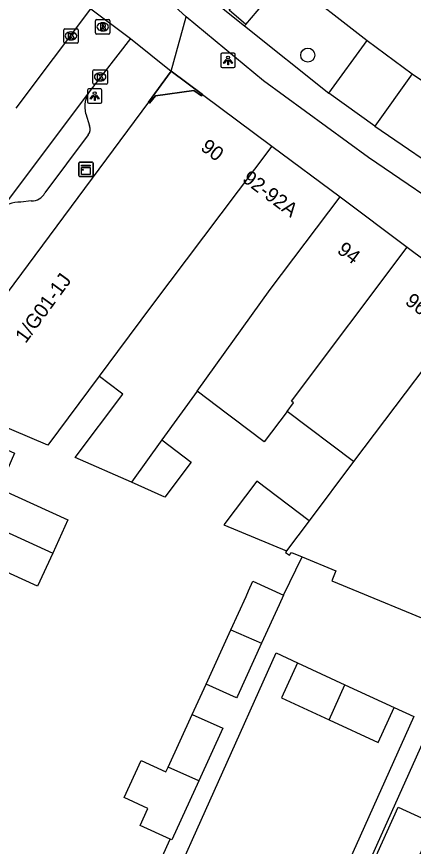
# Model space of a CAD drawing. Extents: x 161845 to 162341, y 381620 to 382158.
# Drawn here: x 162123.1 to 162150.7, y 381792.3 to 381850 of the extents above; entities that cross this region are included whole.
import ezdxf

# ---------------------------------------------------------------- set-up
doc = ezdxf.new("R2010")
doc.units = 0
for name, color, linetype in [('IMGEO_Berm_groen', 7, 'Continuous'), ('IMGEO_Boom', 7, 'Continuous'), ('IMGEO_Groenvoorziening', 7, 'Continuous'), ('IMGEO_Kast', 7, 'Continuous'), ('IMGEO_Kolk', 7, 'Continuous'), ('IMGEO_Lichtpunt', 7, 'Continuous'), ('IMGEO_Pand', 7, 'Continuous'), ('IMGEO_Pand_nummerreeks', 7, 'Continuous'), ('IMGEO_Pand_overbouw', 7, 'Continuous'), ('IMGEO_Rijbaan_lokaal_gesloten', 7, 'Continuous'), ('IMGEO_Rijbaan_lokaal_open', 7, 'Continuous'), ('IMGEO_Rioolput', 7, 'Continuous'), ('IMGEO_Voetpad_gesloten', 7, 'Continuous'), ('IMGEO_Voetpad_open', 7, 'Continuous')]:
    doc.layers.add(name, color=color, linetype=linetype)

msp = doc.modelspace()

# ---------------------------------------------------------------- linework, layer by layer
at = {"layer": 'IMGEO_Berm_groen'}
for points in [[(162139.024, 381849.428), (162140.224, 381850.815)], [(162138.949, 381849.346), (162139.024, 381849.428)]]:
    msp.add_lwpolyline(points, dxfattribs=at)
at = {"layer": 'IMGEO_Boom'}
msp.add_circle((162143.338, 381847.307), 0.489, dxfattribs=at)
at = {"layer": 'IMGEO_Groenvoorziening'}
msp.add_lwpolyline([(162139.024, 381849.428), (162137.867, 381850.429), (162139.067, 381851.816), (162139.757, 381851.219), (162140.224, 381850.815)], dxfattribs=at)
at = {"layer": 'IMGEO_Kast'}
for p, q in [((162127.417, 381838.946), (162127.417, 381839.787)), ((162127.417, 381839.787), (162127.417, 381838.946)), ((162127.492, 381839.871), (162128.333, 381839.871)), ((162128.333, 381839.871), (162127.492, 381839.871)), ((162128.417, 381839.796), (162128.417, 381838.955)), ((162128.417, 381838.955), (162128.417, 381839.796)), ((162128.342, 381838.871), (162127.501, 381838.871)), ((162127.501, 381838.871), (162128.342, 381838.871))]:
    msp.add_line(p, q, dxfattribs=at)
for points in [[(162127.612, 381839.661), (162128.212, 381839.661), (162128.212, 381839.576), (162127.612, 381839.576), (162127.612, 381839.661)], [(162127.612, 381839.486), (162128.212, 381839.486), (162128.212, 381838.997), (162127.612, 381838.997), (162127.612, 381839.486)]]:
    msp.add_lwpolyline(points, dxfattribs=at)
msp.add_circle((162127.696, 381839.335), 0.0377, dxfattribs=at)
for centre, start, end in [((162127.495, 381839.793), 92.4484, 184.28452), ((162127.495, 381839.793), 92.4484, 184.28452), ((162128.339, 381839.793), 2.4484, 94.28452), ((162128.339, 381839.793), 2.4484, 94.28452), ((162127.495, 381838.949), 182.4484, 274.28452), ((162127.495, 381838.949), 182.4484, 274.28452), ((162128.339, 381838.949), 272.4484, 4.28452), ((162128.339, 381838.949), 272.4484, 4.28452)]:
    msp.add_arc(centre, 0.0779, start, end, dxfattribs=at)
at = {"layer": 'IMGEO_Kolk'}
for p, q in [((162126.37, 381848.212), (162126.37, 381849.064)), ((162126.445, 381849.138), (162127.297, 381849.138)), ((162126.858, 381848.918), (162126.883, 381848.918)), ((162127.371, 381849.064), (162127.371, 381848.212)), ((162127.297, 381848.138), (162126.445, 381848.138)), ((162126.881, 381848.358), (162126.856, 381848.358)), ((162128.401, 381845.365), (162128.401, 381846.217)), ((162128.476, 381846.291), (162129.328, 381846.291)), ((162128.889, 381846.071), (162128.914, 381846.071)), ((162129.402, 381846.217), (162129.402, 381845.365)), ((162129.328, 381845.291), (162128.476, 381845.291)), ((162128.912, 381845.511), (162128.887, 381845.511))]:
    msp.add_line(p, q, dxfattribs=at)
for points in [[(162126.37, 381848.212), (162126.37, 381849.064)], [(162126.445, 381849.138), (162127.297, 381849.138)], [(162126.691, 381848.838), (162126.814, 381848.838), (162126.814, 381848.687), (162126.944, 381848.838), (162127.108, 381848.838), (162126.962, 381848.687), (162127.115, 381848.438), (162126.963, 381848.438), (162126.878, 381848.602), (162126.814, 381848.535), (162126.814, 381848.438), (162126.691, 381848.438), (162126.691, 381848.838)], [(162127.371, 381849.064), (162127.371, 381848.212)], [(162127.297, 381848.138), (162126.445, 381848.138)], [(162128.401, 381845.365), (162128.401, 381846.217)], [(162128.476, 381846.291), (162129.328, 381846.291)], [(162128.722, 381845.991), (162128.845, 381845.991), (162128.845, 381845.84), (162128.975, 381845.991), (162129.139, 381845.991), (162128.993, 381845.84), (162129.146, 381845.591), (162128.994, 381845.591), (162128.909, 381845.755), (162128.845, 381845.688), (162128.845, 381845.591), (162128.722, 381845.591), (162128.722, 381845.991)], [(162129.402, 381846.217), (162129.402, 381845.365)], [(162129.328, 381845.291), (162128.476, 381845.291)]]:
    msp.add_lwpolyline(points, dxfattribs=at)
for centre, start, end in [((162126.447, 381849.062), 91.55205, 178.44795), ((162126.447, 381849.062), 91.55205, 178.44795), ((162127.295, 381849.062), 1.55205, 88.44795), ((162127.295, 381849.062), 1.55205, 88.44795), ((162126.447, 381848.214), 181.55205, 268.44795), ((162126.447, 381848.214), 181.55205, 268.44795), ((162127.295, 381848.214), 271.55205, 358.44795), ((162127.295, 381848.214), 271.55205, 358.44795), ((162128.478, 381846.215), 91.55205, 178.44795), ((162128.478, 381846.215), 91.55205, 178.44795), ((162129.326, 381846.215), 1.55205, 88.44795), ((162129.326, 381846.215), 1.55205, 88.44795), ((162128.478, 381845.367), 181.55205, 268.44795), ((162128.478, 381845.367), 181.55205, 268.44795), ((162129.326, 381845.367), 271.55205, 358.44795), ((162129.326, 381845.367), 271.55205, 358.44795)]:
    msp.add_arc(centre, 0.0765, start, end, dxfattribs=at)
for centre, major_axis, ratio, start_param, end_param in [((162126.857, 381848.638), (-0.387, 0.002), 0.722429, 4.712389, 7.853982), ((162126.882, 381848.638), (-0.39, 0.002), 0.717154, 1.570796, 4.712389), ((162128.888, 381845.791), (-0.387, 0.002), 0.722429, 4.712389, 7.853982), ((162128.913, 381845.791), (-0.39, 0.002), 0.717154, 1.570796, 4.712389)]:
    msp.add_ellipse(centre, major_axis=major_axis, ratio=ratio, start_param=start_param, end_param=end_param, dxfattribs=at)
at = {"layer": 'IMGEO_Lichtpunt'}
for p, q in [((162137.299, 381847.342), (162137.299, 381846.535)), ((162137.299, 381847.342), (162137.299, 381846.535)), ((162138.201, 381847.437), (162137.393, 381847.437)), ((162138.201, 381847.437), (162137.393, 381847.437)), ((162138.295, 381846.535), (162138.295, 381847.342)), ((162138.295, 381846.535), (162138.295, 381847.342)), ((162137.393, 381846.441), (162138.201, 381846.441)), ((162137.393, 381846.441), (162138.201, 381846.441)), ((162128.022, 381844.86), (162128.022, 381844.053)), ((162128.022, 381844.86), (162128.022, 381844.053)), ((162128.924, 381844.955), (162128.116, 381844.955)), ((162128.924, 381844.955), (162128.116, 381844.955)), ((162129.018, 381844.053), (162129.018, 381844.86)), ((162129.018, 381844.053), (162129.018, 381844.86)), ((162128.116, 381843.959), (162128.924, 381843.959)), ((162128.116, 381843.959), (162128.924, 381843.959))]:
    msp.add_line(p, q, dxfattribs=at)
for points in [[(162137.673, 381847.006), (162137.712, 381846.978), (162137.524, 381846.716), (162137.486, 381846.743), (162137.673, 381847.006)], [(162137.775, 381846.958), (162137.822, 381846.958), (162137.822, 381846.636), (162137.775, 381846.636), (162137.775, 381846.958)], [(162137.885, 381846.978), (162137.923, 381847.005), (162138.11, 381846.743), (162138.071, 381846.715), (162137.885, 381846.978)], [(162128.396, 381844.524), (162128.435, 381844.496), (162128.247, 381844.234), (162128.209, 381844.261), (162128.396, 381844.524)], [(162128.498, 381844.476), (162128.545, 381844.476), (162128.545, 381844.154), (162128.498, 381844.154), (162128.498, 381844.476)], [(162128.608, 381844.496), (162128.646, 381844.523), (162128.833, 381844.261), (162128.794, 381844.233), (162128.608, 381844.496)]]:
    msp.add_lwpolyline(points, dxfattribs=at)
for centre in [(162137.798, 381847.14), (162128.521, 381844.658)]:
    msp.add_circle(centre, 0.0994, dxfattribs=at)
for centre, start, end in [((162137.393, 381847.342), 90, 180), ((162137.393, 381847.342), 90, 180), ((162138.201, 381847.342), 0, 90), ((162138.201, 381847.342), 0, 90), ((162137.393, 381846.535), 180, 270), ((162137.393, 381846.535), 180, 270), ((162138.201, 381846.535), 270, 0), ((162138.201, 381846.535), 270, 360), ((162128.116, 381844.86), 90, 180), ((162128.116, 381844.86), 90, 180), ((162128.924, 381844.86), 0, 90), ((162128.924, 381844.86), 0, 90), ((162128.116, 381844.053), 180, 270), ((162128.116, 381844.053), 180, 270), ((162128.924, 381844.053), 270, 0), ((162128.924, 381844.053), 270, 360)]:
    msp.add_arc(centre, 0.0946, start, end, dxfattribs=at)
at = {"layer": 'IMGEO_Pand'}
for points in [[(162136.021, 381844.574), (162135.955, 381844.486), (162135.42, 381844.856), (162132.747, 381844.485), (162132.343, 381843.968), (162132.255, 381844.037)], [(162132.255, 381844.037), (162118.958, 381826.112), (162117.736, 381823.377)], [(162136.021, 381844.574), (162140.849, 381840.974)], [(162140.849, 381840.974), (162132.55, 381829.958), (162130.117, 381826.699), (162128.831, 381824.976)], [(162140.849, 381840.974), (162145.582, 381837.445)], [(162135.643, 381823.948), (162140.729, 381831.002), (162145.582, 381837.445)], [(162145.582, 381837.445), (162150.263, 381833.955)], [(162141.902, 381822.537), (162142.358, 381823.143), (162142.204, 381823.258), (162150.263, 381833.955)], [(162150.263, 381833.955), (162155.076, 381830.366)], [(162155.076, 381830.366), (162146.531, 381819.056)], [(162128.831, 381824.976), (162125.256, 381820.187), (162117.736, 381823.377)], [(162131.073, 381817.61), (162127.171, 381819.339), (162130.484, 381823.73), (162129.428, 381824.526), (162128.939, 381824.895), (162128.831, 381824.976)], [(162135.643, 381823.948), (162133.193, 381820.551)], [(162141.902, 381822.537), (162140.311, 381820.424), (162138.121, 381822.077), (162137.754, 381822.354), (162135.643, 381823.948)], [(162116.671, 381822.492), (162122.955, 381819.625), (162121.858, 381817.172), (162126.648, 381814.998), (162125.6, 381812.69)], [(162146.531, 381819.056), (162141.902, 381822.537)], [(162133.193, 381820.551), (162135.232, 381819.012), (162133.397, 381816.58), (162131.073, 381817.61)], [(162133.193, 381820.551), (162131.073, 381817.61)], [(162146.531, 381819.056), (162143.433, 381814.937)], [(162114.518, 381817.746), (162125.6, 381812.69)], [(162143.433, 381814.937), (162139.789, 381817.677), (162137.514, 381814.652), (162141.851, 381812.833)], [(162143.433, 381814.937), (162141.851, 381812.833)], [(162125.6, 381812.69), (162124.553, 381810.382), (162119.703, 381812.583), (162118.569, 381810.085)], [(162141.851, 381812.833), (162141.78, 381812.738), (162142.078, 381812.552), (162142.216, 381812.736), (162142.94, 381812.435)], [(162142.94, 381812.435), (162145.297, 381811.453), (162145.01, 381810.757), (162153.095, 381807.419)], [(162137.993, 381807.358), (162139.052, 381809.679), (162139.228, 381810.066), (162139.53, 381810.727), (162141.649, 381809.761)], [(162141.649, 381809.761), (162141.347, 381809.1), (162140.122, 381806.415)], [(162136.265, 381803.571), (162137.993, 381807.358)], [(162137.993, 381807.358), (162140.122, 381806.415)], [(162140.122, 381806.415), (162138.442, 381802.731), (162138.394, 381802.627), (162136.265, 381803.571)], [(162142.635, 381805.055), (162141.51, 381802.623), (162144.829, 381801.088)], [(162142.635, 381805.055), (162145.926, 381803.533)], [(162144.829, 381801.088), (162145.926, 381803.533)], [(162145.926, 381803.533), (162149.358, 381801.946)], [(162144.829, 381801.088), (162148.233, 381799.514), (162149.358, 381801.946)], [(162133.636, 381797.806), (162135.306, 381801.468)], [(162135.306, 381801.468), (162137.435, 381800.524), (162135.765, 381796.863)], [(162133.775, 381792.798), (162131.681, 381793.753), (162132.223, 381794.94), (162130.572, 381795.693), (162131.744, 381798.261), (162133.481, 381797.468), (162133.636, 381797.806)], [(162135.765, 381796.863), (162133.636, 381797.806)], [(162135.765, 381796.863), (162133.887, 381792.747), (162133.775, 381792.798)], [(162147.772, 381790.915), (162149.622, 381795.011), (162152.11, 381793.887), (162150.263, 381789.796)]]:
    msp.add_lwpolyline(points, dxfattribs=at)
at = {"layer": 'IMGEO_Pand_overbouw'}
msp.add_lwpolyline([(162132.255, 381844.037), (162132.343, 381843.968), (162132.747, 381844.485), (162135.42, 381844.856), (162135.955, 381844.486), (162136.021, 381844.574), (162133.845, 381846.181)], close=True, dxfattribs=at)
at = {"layer": 'IMGEO_Rijbaan_lokaal_gesloten'}
for points in [[(162142.172, 381852.464), (162147.466, 381848.311)], [(162147.466, 381848.311), (162150.594, 381846.009)], [(162150.594, 381846.009), (162156.657, 381841.909)]]:
    msp.add_lwpolyline(points, dxfattribs=at)
at = {"layer": 'IMGEO_Rijbaan_lokaal_open'}
for points in [[(162123.069, 381843.607), (162128.26, 381850.52)], [(162128.26, 381850.52), (162131.013, 381848.456)], [(162131.013, 381848.456), (162128.199, 381844.856)], [(162128.199, 381844.856), (162121.878, 381836.437)]]:
    msp.add_lwpolyline(points, dxfattribs=at)
at = {"layer": 'IMGEO_Rioolput'}
for p, q in [((162128.581, 381848.845), (162128.581, 381849.697)), ((162128.656, 381849.771), (162129.508, 381849.771)), ((162129.069, 381849.551), (162129.094, 381849.551)), ((162129.582, 381849.697), (162129.582, 381848.845)), ((162129.508, 381848.771), (162128.656, 381848.771)), ((162129.092, 381848.991), (162129.067, 381848.991))]:
    msp.add_line(p, q, dxfattribs=at)
for points in [[(162128.581, 381848.845), (162128.581, 381849.697)], [(162128.656, 381849.771), (162129.508, 381849.771)], [(162129.17, 381849.469), (162128.918, 381849.471), (162128.918, 381849.071)], [(162128.918, 381849.071), (162129.042, 381849.071), (162129.042, 381849.233), (162129.053, 381849.233)], [(162129.096, 381849.39), (162129.042, 381849.39), (162129.042, 381849.309)], [(162129.042, 381849.309), (162129.094, 381849.309)], [(162129.582, 381849.697), (162129.582, 381848.845)], [(162129.508, 381848.771), (162128.656, 381848.771)], [(162129.1, 381849.204), (162129.171, 381849.071), (162129.311, 381849.071), (162129.246, 381849.197)]]:
    msp.add_lwpolyline(points, dxfattribs=at)
for centre, radius, start, end in [((162128.658, 381849.695), 0.0765, 91.55205, 178.44795), ((162128.658, 381849.695), 0.0765, 91.55205, 178.44795), ((162129.052, 381849.18), 0.0533, 26.02933, 88.69889), ((162129.078, 381849.498), 0.19, 274.7715, 282.96867), ((162129.102, 381849.294), 0.0964, 77.00612, 93.18647), ((162129.116, 381849.351), 0.0378, 276.66336, 79.67722), ((162129.169, 381849.359), 0.109, 350.36119, 89.41601), ((162129.167, 381849.359), 0.112, 277.58423, 350.98172), ((162129.151, 381849.144), 0.108, 29.51342, 73.79051), ((162129.506, 381849.695), 0.0765, 1.55205, 88.44795), ((162129.506, 381849.695), 0.0765, 1.55205, 88.44795), ((162128.658, 381848.847), 0.0765, 181.55205, 268.44795), ((162128.658, 381848.847), 0.0765, 181.55205, 268.44795), ((162129.506, 381848.847), 0.0765, 271.55205, 358.44795), ((162129.506, 381848.847), 0.0765, 271.55205, 358.44795)]:
    msp.add_arc(centre, radius, start, end, dxfattribs=at)
for centre, major_axis, ratio, start_param, end_param in [((162129.068, 381849.271), (-0.387, 0.002), 0.722429, 4.712389, 7.853982), ((162129.093, 381849.271), (-0.39, 0.002), 0.717154, 1.570796, 4.712389)]:
    msp.add_ellipse(centre, major_axis=major_axis, ratio=ratio, start_param=start_param, end_param=end_param, dxfattribs=at)
at = {"layer": 'IMGEO_Voetpad_gesloten'}
for points in [[(162134.882, 381849.978), (162130.429, 381854.037), (162125.545, 381859.011), (162121.54, 381863.477), (162117.602, 381868.047), (162113.764, 381872.679), (162110.7, 381876.627), (162107.813, 381880.741), (162103.406, 381887.421), (162102.392, 381889.138), (162058.476, 381968.271)], [(162136.067, 381851.659), (162138.949, 381849.346)], [(162289.497, 381752.523), (162284.268, 381764.473), (162282.076, 381768.974), (162280.091, 381772.447), (162277.759, 381775.733), (162275.072, 381778.709), (162271.828, 381781.089), (162266.754, 381783.434), (162197.313, 381814.891), (162168.761, 381826.912), (162165.238, 381828.801), (162160.086, 381831.935), (162154.18, 381835.7), (162147.552, 381840.181), (162140.263, 381845.513), (162134.882, 381849.978)], [(162138.949, 381849.346), (162144.794, 381844.655)], [(162147.999, 381842.366), (162144.794, 381844.655)], [(162147.999, 381842.366), (162153.639, 381838.523)]]:
    msp.add_lwpolyline(points, dxfattribs=at)
at = {"layer": 'IMGEO_Voetpad_open'}
for points in [[(162133.845, 381846.181), (162134.882, 381849.978)], [(162131.013, 381848.456), (162133.845, 381846.181)], [(162144.794, 381844.655), (162147.466, 381848.311)], [(162132.255, 381844.037), (162133.845, 381846.181)], [(162133.845, 381846.181), (162136.021, 381844.574)], [(162150.594, 381846.009), (162147.999, 381842.366)], [(162127.895, 381843.225), (162128.152, 381842.401)], [(162128.066, 381841.754), (162125.049, 381837.729)], [(162124.112, 381837.179), (162123.389, 381837.075)], [(162141.649, 381809.761), (162142.94, 381812.435)], [(162133.113, 381787.852), (162141.138, 381805.747), (162142.635, 381805.055)], [(162135.306, 381801.468), (162136.265, 381803.571)], [(162149.358, 381801.946), (162150.709, 381801.321), (162142.742, 381783.559)], [(162152.366, 381800.551), (162151.891, 381800.771), (162148.117, 381792.355), (162144.98, 381785.36)], [(162132.773, 381790.595), (162133.775, 381792.798)]]:
    msp.add_lwpolyline(points, dxfattribs=at)
for centre, radius, start, end in [((162129.825, 381843.709), 1.99, 144.80828, 194.07546), ((162127.572, 381842.149), 0.632, 321.35449, 23.50263), ((162124.158, 381838.174), 0.996, 267.37056, 333.45358), ((162123.227, 381835.35), 1.733, 84.64418, 141.13836)]:
    msp.add_arc(centre, radius, start, end, dxfattribs=at)

# ---------------------------------------------------------------- texts
at = {"layer": 'IMGEO_Pand_nummerreeks'}
for s, rotation, p in [('90', 323.02703, (162135.819, 381840.758)), ('92-92A', 323.02703, (162138.722, 381838.572)), ('94', 323.02703, (162145.315, 381833.61)), ('1/G01-1J', 53.97262, (162123.719, 381827.216)), ('96', 323.02895, (162150.045, 381830.048))]:
    msp.add_text(s, height=1, rotation=rotation, dxfattribs=at).set_placement(p)

doc.saveas('drawing.dxf')
